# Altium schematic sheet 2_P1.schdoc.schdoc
size 309 x 223 mm; Symbol: Sheet-Symbol_A4; Device: Sheet-Symbol_A4; @Project Name: LuxBadge2024; @Page Count: 2; @Update Date: 2024-07-21; @Create Date: 2024-06-06; @Schematic Name: Schematic1; @Page No: 1; @Page Name: P1; Company: EasyEDA.com; Reviewed: EasyEDA; Version: V0.1; Page Size: A4; Part Number: JLCPCB-002; Drawn: EasyEDA
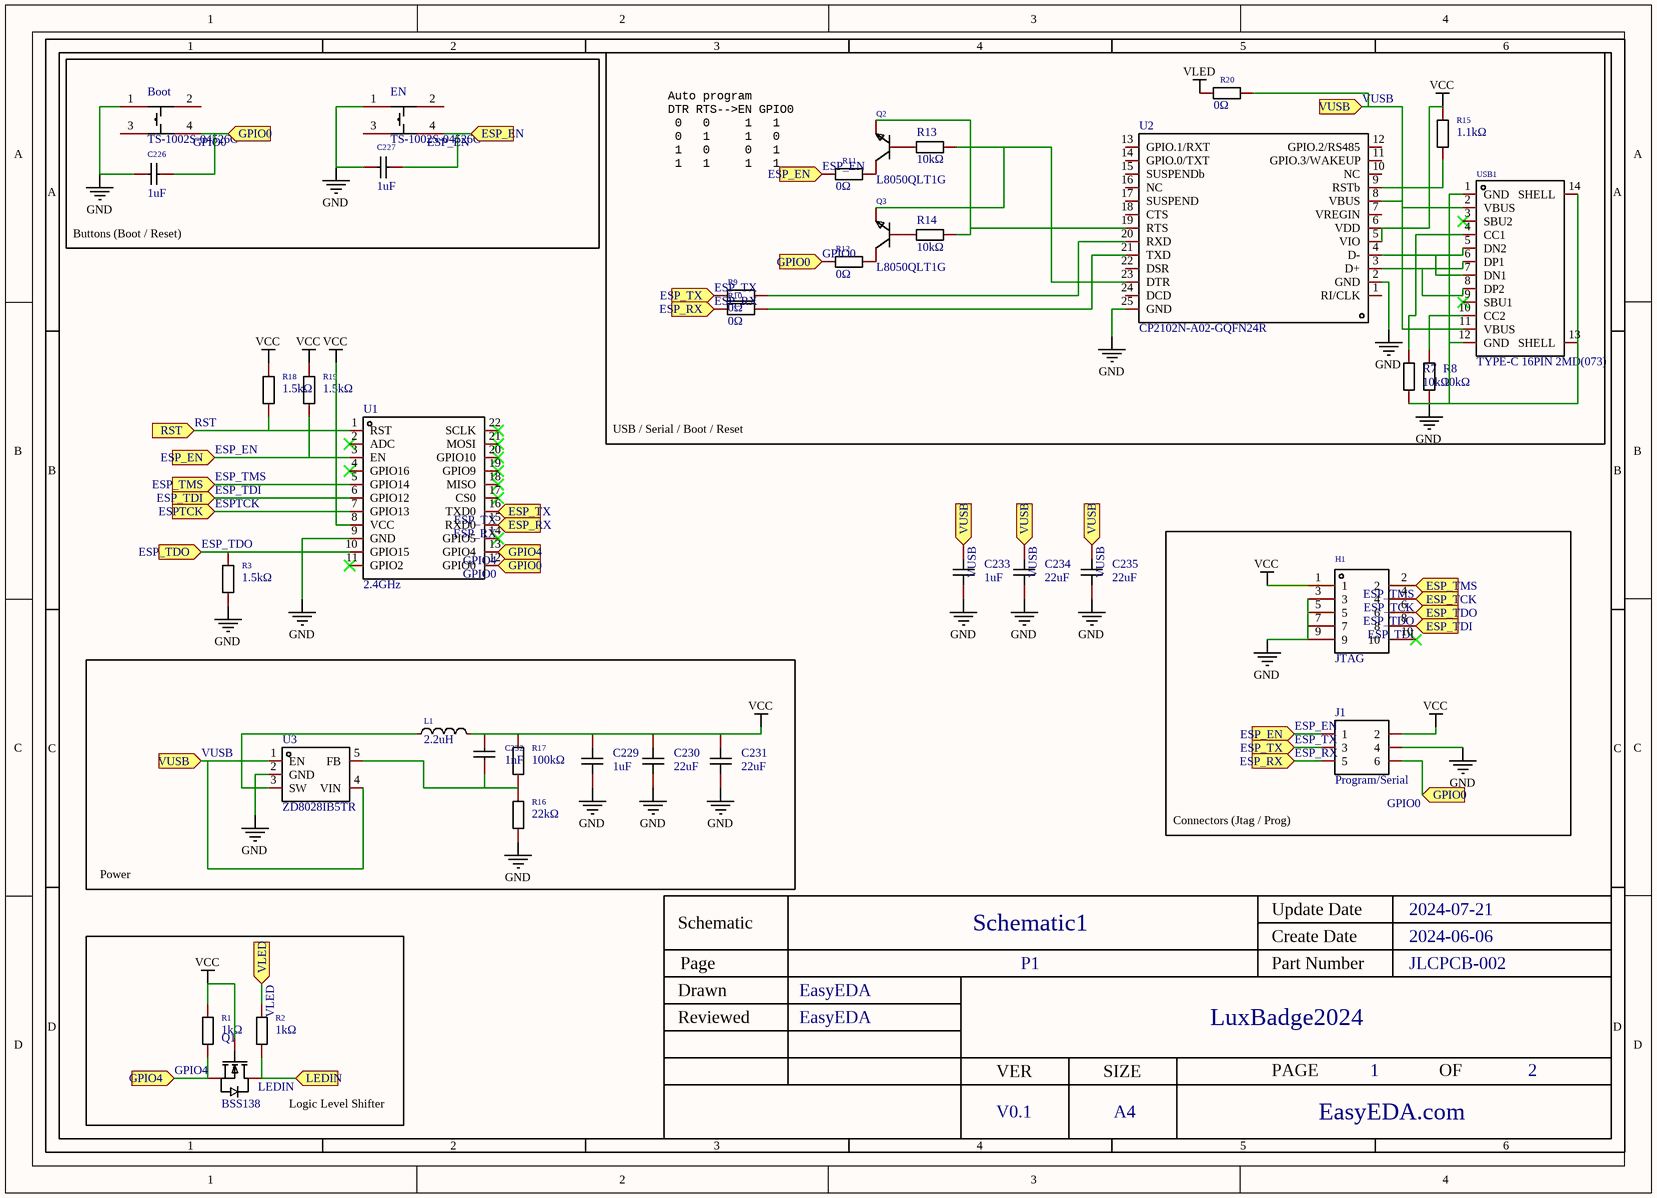
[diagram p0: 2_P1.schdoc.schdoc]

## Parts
Boot  TS-1002S-04526C  [SW-SMD_4P-L6.0-W6.0-P4.50-LS9.0-2]
C226  1uF  [C0402]
C227  1uF  [C0402]
C229  1uF  [C0603]
C230  22uF  [C0805]
C231  22uF  [C0805]
C232  1nF  [C0603]
C233  1uF  [C0603]
C234  22uF  [C0805]
C235  22uF  [C0805]
EN  TS-1002S-04526C  [SW-SMD_4P-L6.0-W6.0-P4.50-LS9.0-2]
H1  JTAG  [HDR-TH_10P-P2.54-V-M-R2-C5-S2.54]
J1  Program/Serial  [HDR-TH_6P-P2.54-V-M-R2-C3-S2.54-1]
L1  2.2uH  [IND-SMD_L2.0-W1.6_MHCHL201610A-1R0M-Q8A]
Q1  BSS138  [SOT-23-3_L2.9-W1.3-P1.90-LS2.4-BR]
Q2  L8050QLT1G  [SOT-23-3_L2.9-W1.3-P1.90-LS2.4-BR]
Q3  L8050QLT1G  [SOT-23-3_L2.9-W1.3-P1.90-LS2.4-BR]
R1  1kΩ  [R0603]
R2  1kΩ  [R0603]
R3  1.5kΩ  [R0603]
R7  10kΩ  [R0402]
R8  10kΩ  [R0402]
R9  0Ω  [R0603]
R10  0Ω  [R0603]
R11  0Ω  [R0603]
R12  0Ω  [R0603]
R13  10kΩ  [R0402]
R14  10kΩ  [R0402]
R15  1.1kΩ  [R0402]
R16  22kΩ  [R0603]
R17  100kΩ  [R0603]
R18  1.5kΩ  [R0603]
R19  1.5kΩ  [R0603]
R20  0Ω  [R0603]
U1  2.4GHz  [WIFIM-SMD_ESP-12F-ESP8266MOD]
U2  CP2102N-A02-GQFN24R  [QFN-24_L4.0-W4.0-P0.50-TL-EP2.6]
U3  ZD8028IB5TR  [SOT-23-5_L2.9-W1.6-P0.95-LS2.9-BL]
USB1  TYPE-C 16PIN 2MD(073)  [USB-C-SMD_TYPE-C-6PIN-2MD-073]

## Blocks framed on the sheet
Buttons (Boot / Reset): Boot C226 C227 EN
USB / Serial / Boot / Reset: Q2 Q3 R7-R15 R20 U2 USB1
Connectors (Jtag / Prog): H1 J1
Power: C229-C232 L1 R16 R17 U3
Logic Level Shifter: Q1 R1 R2

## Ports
ESP_EN (in), ESP_RX (in), ESP_TCK (in), ESP_TDI (in), ESP_TDO (in), ESP_TMS (in), ESP_TX (in), ESPTCK (in), GPIO0 (in), GPIO4 (in), LEDIN (in), RST (in), VLED (in), VUSB (in)

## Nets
GND: Boot.1 C226.2 C227.2 C229.1 C230.1 C231.1 C233.1 C234.1 C235.1 EN.1 H1.3 H1.5 H1.7 H1.9 J1.4 R3.1 R7.1 R8.1 R16.1 U1.9(GND) U2.2(GND) U2.25(GND) U3.2(GND) USB1.1(GND) USB1.12(GND) USB1.13(SHELL) USB1.14(SHELL)
VCC: C229.2 C230.2 C231.2 C232.2 H1.1 J1.2 L1.2 Q1.1(G) R1.2 R15.2 R17.2 R18.2 R19.2 U1.8(VCC) U2.5(VIO) U2.6(VDD)
VLED: R2.2 R20.1 ; port VLED
ESP_EN: C227.1 EN.4 J1.1 R11.1 R19.1 U1.3(EN) ; port ESP_EN
ESP_RX: J1.5 R10.1 U1.15(RXD0) ; port ESP_RX
ESP_TCK: H1.4 ; port ESP_TCK
ESP_TDI: H1.8 U1.6(GPIO12) ; port ESP_TDI
ESP_TDO: H1.6 R3.2 U1.10(GPIO15) ; port ESP_TDO
ESP_TMS: H1.2 U1.5(GPIO14) ; port ESP_TMS
ESP_TX: J1.3 R9.1 U1.16(TXD0) ; port ESP_TX
ESPTCK: U1.7(GPIO13) ; port ESPTCK
GPIO0: Boot.4 C226.1 J1.6 R12.1 U1.12(GPIO0) ; port GPIO0
GPIO4: Q1.2(S) R1.1 U1.13(GPIO4) ; port GPIO4
LEDIN: Q1.3(D) R2.1 ; port LEDIN
RST: R18.1 U1.1(RST) ; port RST
VUSB: C233.2 C234.2 C235.2 R20.2 U2.8(VBUS) U3.1(EN) U3.4(VIN) USB1.2(VBUS) USB1.11(VBUS) ; port VUSB
NetC232_1: C232.1 R16.2 R17.1 U3.5(FB)
NetL1_1: L1.1 U3.3(SW)
NetQ2_1: Q2.1(B) R13.1
NetQ2_2: Q2.2(E) R14.2 U2.19(RTS)
NetQ2_3: Q2.3(C) R11.2
NetQ3_1: Q3.1(B) R14.1
NetQ3_2: Q3.2(E) R13.2 U2.23(DTR)
NetQ3_3: Q3.3(C) R12.2
NetR7_2: R7.2 USB1.4(CC1)
NetR8_2: R8.2 USB1.10(CC2)
NetR9_2: R9.2 U2.20(RXD)
NetR10_2: R10.2 U2.21(TXD)
NetR15_1: R15.1 U2.9(RSTb)
NetU2_3: U2.3(D+) USB1.6(DP1) USB1.8(DP2)
NetU2_4: U2.4(D-) USB1.5(DN2) USB1.7(DN1)

Not connected (* = marked no-connect by the designer): Boot 2 3; EN 2 3; H1 10*; U1 2(ADC)* 4(GPIO16)* 11(GPIO2)* 14(GPIO5)* 17(CS0)* 18(MISO)* 19(GPIO9)* 20(GPIO10)* 21(MOSI)* 22(SCLK)*; U2 1(RI/CLK) 7(VREGIN) 10(NC) 11(GPIO.3/WAKEUP) 12(GPIO.2/RS485) 13(GPIO.1/RXT) 14(GPIO.0/TXT) 15(SUSPENDb) 16(NC) 17(SUSPEND) 18(CTS) 22(DSR) 24(DCD); USB1 3(SBU2)* 9(SBU1)*

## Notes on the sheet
- Auto program
  DTR RTS-->EN GPIO0
  0   0     1   1
  0   1     1   0
  1   0     0   1
  1   1     1   1

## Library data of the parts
Boot EN = TS-1002S-04526C: Manufacturer: XUNPU(讯普); Add into BOM: yes; Circuit: SPST; Actuator Style: Round Button; Switch Length: 6mm; Switch Height: 4.5mm; Contact Current: 50mA; Voltage Rating (DC): 12V; Description: Circuit:SPST Actuator Style:Round Button Mounting Style:Brick nogging Switch Length:6mm Switch Width:6mm Switch Height:4.5mm Contact Current:50mA Voltage Rating (DC):12V With Lamp:- Mechanical Life:-
C226 C227 = CL05A105KP5NNNC: Manufacturer: SAMSUNG(三星); Add into BOM: yes; Tolerance: ±10%; Description: Capacitance: Tolerance:±10% Tolerance:±10% Voltage Rated: Temperature Coefficient:
C229 C233 = CL10A105KB8NNNC: Manufacturer: SAMSUNG(三星); Add into BOM: yes; Tolerance: ±10%; Description: Capacitance: Tolerance:±10% Tolerance:±10% Voltage Rated: Temperature Coefficient:
C230 C231 C234 C235 = CL21A226MAQNNNE: Manufacturer: SAMSUNG(三星); Add into BOM: yes; Tolerance: ±20%; Description: Capacitance: Tolerance:±20% Tolerance:±20% Voltage Rated: Temperature Coefficient:
C232 = CC0603KRX7R9BB102: Manufacturer: YAGEO(国巨); Add into BOM: yes; Tolerance: ±10%; Description: Capacitance: Tolerance:±10% Tolerance:±10% Voltage Rated: Temperature Coefficient:
H1 = B-2100S10P-B110: Manufacturer: Ckmtw(灿科盟); Symbol: 210S-2*5P L=11.6MMGold-plated black; Add into BOM: no; Convert to PCB: yes; Pin Structure: 2x5P; Pitch: 2.54mm; Description: Pin Structure:2x5P Pitch:2.54mm Row Spacing:2.54mm Circluar Pins/Square Pins:- Mounting Type:Straight Number of Rows:双排 Number of Pins:10P Current Rating (Max):- Voltage Rating (Max):- Length of Mating Pin:6mm Insulation Height:2.54mm Length of End Connec
J1 = 2.54-2*3P针: Manufacturer: BOOMELE(博穆精密); Symbol: Header-Male-2.54_2x3; Add into BOM: no; Convert to PCB: yes; Pitch: 2.54mm; Description: Pin Structure:- Pitch:2.54mm Row Spacing:- Circluar Pins/Square Pins:- Mounting Type:Straight Number of Rows:双排 Number of Pins:6P Current Rating (Max):- Voltage Rating (Max):- Length of Mating Pin:- Insulation Height:- Contact Material: Contact Plating:-
L1 = WIP201610P-2R2ML: Manufacturer: INPAQ(佳邦); Add into BOM: yes; Tolerance: ±20%; Description: Inductance: Tolerance:±20% Tolerance:±20% Rated Current: Saturation Current (Isat):- DC Resistance (DCR): Q @ Freq:- Frequency - Self Resonant:- Ratings:
Q1 = BSS138_C489349: Type: Drain Source Voltage (Vdss): Continuous Drain Current (Id): Power Dissipation (Pd): Drain Source On Resistance (RDS(on)@Vgs,Id):2.5Ω@10V,220mA Gate Threshold Voltage (Vgs(th)@Id):1.5V@250A; Manufacturer: KEXIN(科信); Add into BOM: yes
Q2 Q3 = L8050QLT1G: Manufacturer: LRC(乐山无线电); Add into BOM: yes; Description: Transistor Type: Collector Current (Ic): Collector-Emitter Breakdown Voltage (Vceo): Power Dissipation (Pd):
R1 R2 = 0603WAJ0102T5E: Manufacturer: UNI-ROYAL(厚声); Add into BOM: yes; Tolerance: ±5%; Temperature Coefficient: ±100ppm/℃; Description: Type:Thick Film Resistors Resistance:1kΩ Tolerance:±5% Tolerance:±5% Power(Watts): Overload Voltage (Max): Temperature Coefficient:±100ppm/℃ Temperature Coefficient:±100ppm/℃ Operating Temperature Range:-55℃~+155℃ Operating Temperature Range:-55℃~+155℃
R3 R18 R19 = 0603WAF1501T5E: Manufacturer: UNI-ROYAL(厚声); Add into BOM: yes; Tolerance: ±1%; Temperature Coefficient: ±100ppm/℃; Description: Type:Thick Film Resistors Resistance:1.5kΩ Tolerance:±1% Tolerance:±1% Power(Watts): Overload Voltage (Max): Temperature Coefficient:±100ppm/℃ Temperature Coefficient:±100ppm/℃ Operating Temperature Range:-55℃~+155℃ Operating Temperature Range:-55℃~+155℃
R7 R8 R13 R14 = 0402WGF1002TCE: Manufacturer: UNI-ROYAL(厚声); Add into BOM: yes; Tolerance: ±1%; Temperature Coefficient: ±100ppm/℃; Description: Type:Thick Film Resistors Resistance:10kΩ Tolerance:±1% Tolerance:±1% Power(Watts): Overload Voltage (Max): Temperature Coefficient:±100ppm/℃ Temperature Coefficient:±100ppm/℃ Operating Temperature Range:-55℃~+155℃ Operating Temperature Range:-55℃~+155℃
R9-R12 R20 = 0603WAF0000T5E: Manufacturer: UNI-ROYAL(厚声); Add into BOM: yes; Tolerance: ±1%; Description: Type:Thick Film Resistors Resistance: Tolerance:±1% Tolerance:±1% Power(Watts): Overload Voltage (Max): Operating Temperature Range:-55℃~+155℃ Operating Temperature Range:-55℃~+155℃
R15 = 0402WGF1101TCE: Manufacturer: UNI-ROYAL(厚声); Add into BOM: yes; Tolerance: ±1%; Temperature Coefficient: ±100ppm/℃; Description: Type:Thick Film Resistors Resistance:1.1kΩ Tolerance:±1% Tolerance:±1% Power(Watts): Overload Voltage (Max): Temperature Coefficient:±100ppm/℃ Temperature Coefficient:±100ppm/℃ Operating Temperature Range:-55℃~+155℃ Operating Temperature Range:-55℃~+155℃
R16 = 0603WAF2202T5E: Manufacturer: UNI-ROYAL(厚声); Add into BOM: yes; Tolerance: ±1%; Temperature Coefficient: ±100ppm/℃; Description: Type:Thick Film Resistors Resistance:22kΩ Tolerance:±1% Tolerance:±1% Power(Watts): Overload Voltage (Max): Temperature Coefficient:±100ppm/℃ Temperature Coefficient:±100ppm/℃ Operating Temperature Range:-55℃~+155℃ Operating Temperature Range:-55℃~+155℃
R17 = RC0603FR-07100KL: Manufacturer: YAGEO(国巨); Add into BOM: yes; Tolerance: ±1%; Temperature Coefficient: ±100ppm/℃; Description: Type:Thick Film Resistors Resistance: Tolerance:±1% Tolerance:±1% Power(Watts): Overload Voltage (Max): Temperature Coefficient:±100ppm/℃ Temperature Coefficient:±100ppm/℃ Operating Temperature Range:-55℃~+155℃ Operating Temperature Range:-55℃~+155℃
U1 = ESP-12F(ESP8266MOD): Manufacturer: Ai-Thinker(安信可); Add into BOM: yes; Core Processor: ESP8266芯片; Support Interface: GPIO；UART；I2C；PWM；SPI；ADC; Antenna Type: 板载PCBAntenna; Output Power: 16dBm; Operating Voltage: 3.3V; Receive  Current: 120mA; Send  Current: 170mA; Sensitivity: -90dBm; Description: Core Processor:ESP8266芯片 Wireless Standard:- Support Interface:GPIO；UART；I2C；PWM；SPI；ADC Frequency:2.4GHz Antenna Type:板载PCBAntenna Output Power:16dBm Output Power:16dBm Operating Voltage:3.3V Operating Voltage:3.3V Receive  Current:120mA Send  Current:17
U2 = CP2102N-A02-GQFN24R: Manufacturer: SKYWORKS/SILICON LABS(芯科); Add into BOM: yes; Applications Function: USB转UART; Protocol: UART; Supply Voltage: 3V~3.6V; Description: Applications Function:USB转UART Protocol:UART Supply Voltage:3V~3.6V Supply Voltage:3V~3.6V Operating Temperature:-40℃~+85℃@(Ta) Operating Temperature:-40℃~+85℃@(Ta)
U3 = ZD8028IB5TR: Manufacturer: Zetta(澜智); Add into BOM: yes; Function: Step-down type; Input Voltage: 2.6V~5.5V; Output Voltage: 1.8V; Output Current (Max): 1.5A; Switching Frequency: 2MHz; Number of Outputs: 1; Quiescent Current (Iq): 55uA; Switch tube (built-in/external): 内置; Description: Function:Step-down type Output Type:- Input Voltage:2.6V~5.5V Input Voltage:2.6V~5.5V Output Voltage:1.8V Output Voltage:1.8V Output Current (Max):1.5A Switching Frequency:2MHz Operating Temperature:-40℃~+80℃ Operating Temperature:-40℃~+80℃ Synchronous Re
USB1 = TYPE-C 16PIN 2MD(073): Manufacturer: SHOU HAN(首韩); Add into BOM: yes; Gender: Female; Number of Ports: 1; Number of Contacts: 16P; Current Rating - Power (Max): 5A; Description: Connector Type:Type-C Standard:- Gender:Female Number of Ports:1 Number of Contacts:16P Mounting Style:卧贴 Current Rating - Power (Max):5A Operating Temperature Range:-25℃~+85℃ Operating Temperature Range:-25℃~+85℃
